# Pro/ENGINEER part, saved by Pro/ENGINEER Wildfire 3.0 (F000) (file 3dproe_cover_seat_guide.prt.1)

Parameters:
  DESCRIPTION = "BRASS BONNET NUT"
  MODELED_BY = "L. CONARD"
  PTC_COMMON_NAME = "BRASS BONNET NUT"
